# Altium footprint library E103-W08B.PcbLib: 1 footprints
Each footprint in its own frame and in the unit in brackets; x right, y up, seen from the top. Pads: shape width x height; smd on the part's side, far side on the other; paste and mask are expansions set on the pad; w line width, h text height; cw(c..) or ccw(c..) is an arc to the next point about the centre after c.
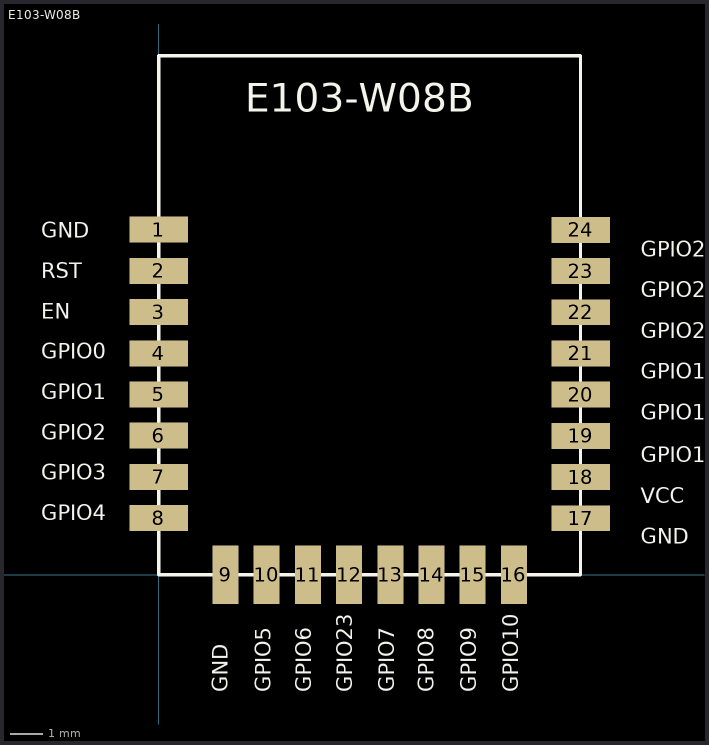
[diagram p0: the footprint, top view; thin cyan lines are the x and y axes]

## E103-W08B [mm]
pads (24):
  rect 1.8x0.8 smd: 1(0,10.64) 2(0,9.37) 3(0,8.1) 4(0,6.83) 5(0,5.56) 6(0,4.29) 7(0,3.02) 8(0,1.75) 17(13,1.745) 18(13,3.015) 19(13,4.285) 20(13,5.555) 21(13,6.825) 22(13,8.095) 23(13,9.365) 24(13,10.635)
  rect 0.8x1.8 smd: 9(2.055,0) 10(3.325,0) 11(4.595,0) 12(5.865,0) 13(7.135,0) 14(8.405,0) 15(9.675,0) 16(10.945,0)
Top Overlay:
  lines w0.1: 0,0 13,0 13,16 0,16 0,0
  text "GPIO23" at 6.121,-3.617 h0.8
  text "GPIO6" at 4.845,-3.617 h0.8
  text "GPIO7" at 7.413,-3.617 h0.8
  text "GPIO8" at 8.632,-3.617 h0.8
  text "GPIO9" at 9.931,-3.617 h0.8
  text "GND" at 2.281,-3.617 h0.8
  text "GPIO10" at 11.231,-3.617 h0.8
  text "GND" at -3.623,10.233 h0.8
  text "RST" at -3.623,8.99 h0.8
  text "EN" at -3.623,7.737 h0.8
  text "GPIO0" at -3.623,6.503 h0.8
  text "GPIO1" at -3.623,5.259 h0.8
  text "GPIO2" at -3.623,4.015 h0.8
  text "GPIO3" at -3.623,2.772 h0.8
  text "GPIO4" at -3.623,1.528 h0.8
  text "GPIO22" at 14.853,9.653 h0.8
  text "GPIO20" at 14.853,7.141 h0.8
  text "GPIO19" at 14.853,5.884 h0.8
  text "GPIO21" at 14.853,8.397 h0.8
  text "GPIO18" at 14.853,4.628 h0.8
  text "GPIO11" at 14.853,3.316 h0.8
  text "VCC" at 14.854,2.06 h0.8
  text "GND" at 14.853,0.804 h0.8
  text "GPIO5" at 3.596,-3.617 h0.8
  text "E103-W08B" at 2.659,13.985 h1.5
